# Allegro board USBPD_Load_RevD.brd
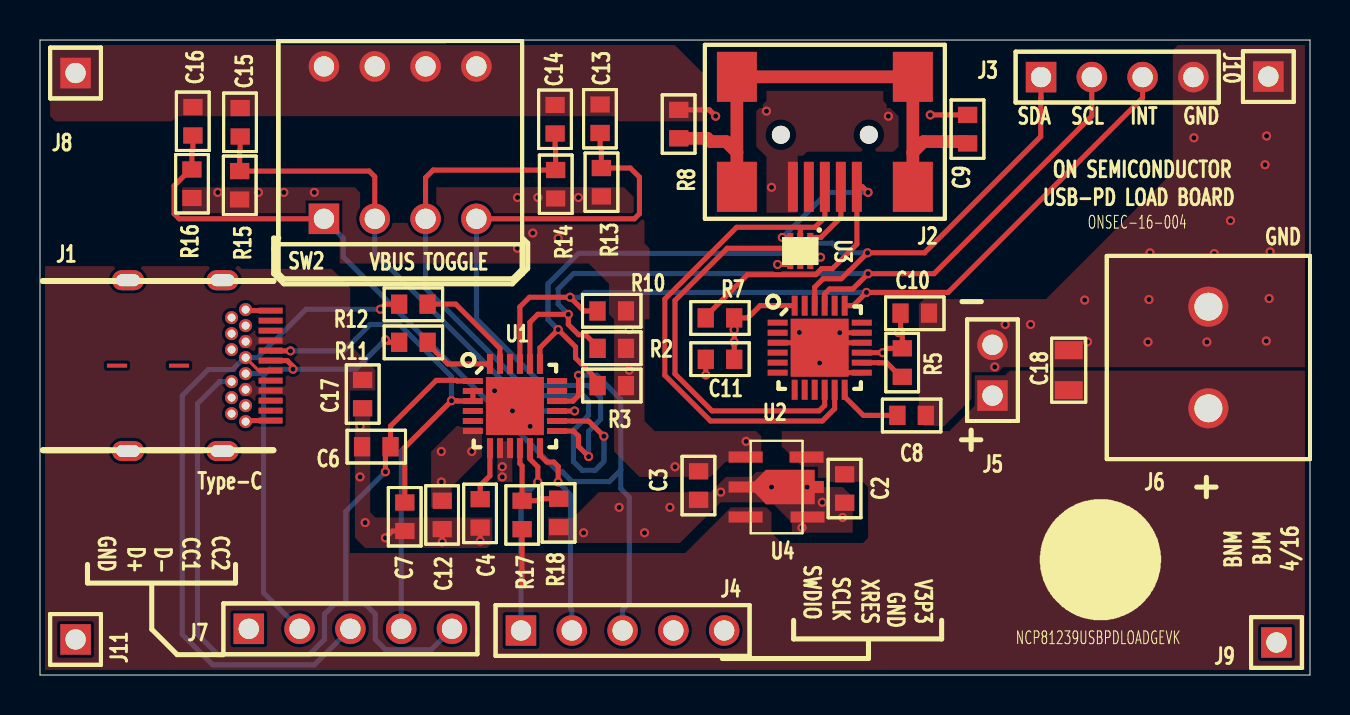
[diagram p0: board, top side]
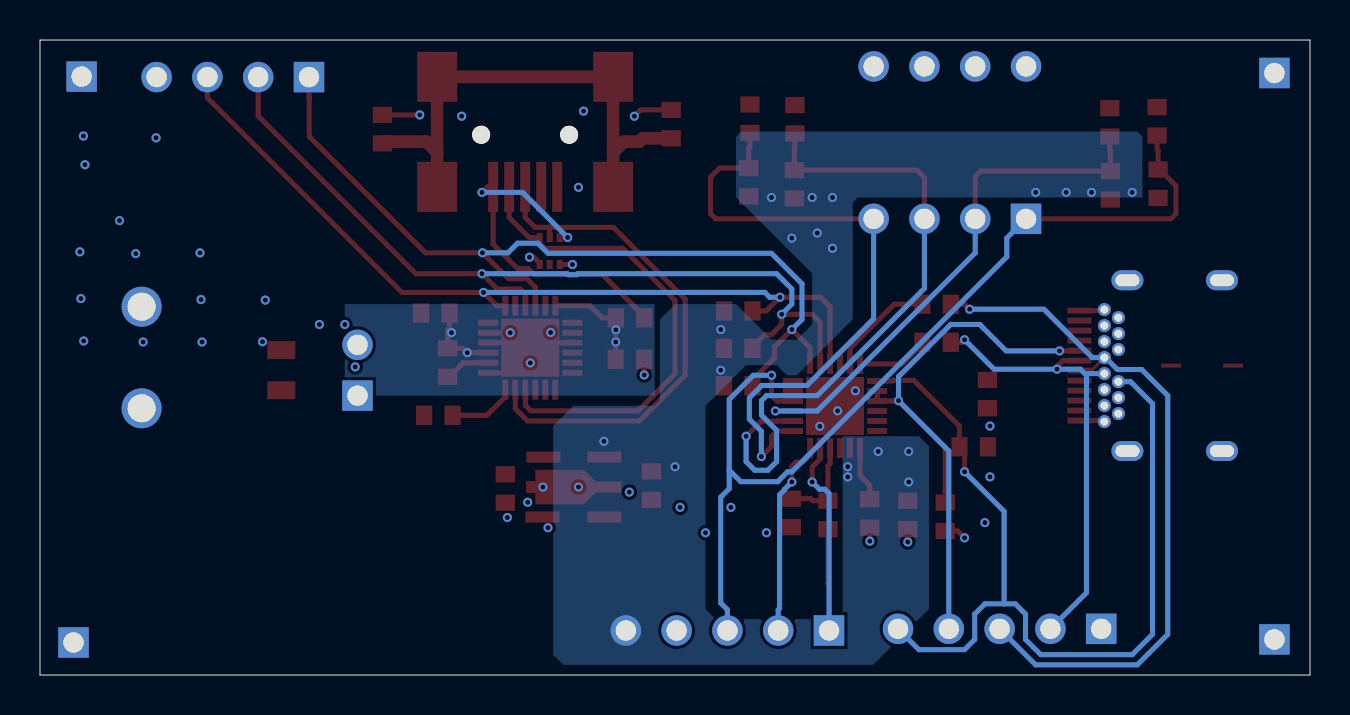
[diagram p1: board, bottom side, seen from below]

Outline 63.5 x 31.75 mm; copper layers: TOP, L2, L3, BOTTOM. Coordinates in mm from the lower left corner of the outline.
Outline path: 0,31.75 0,0 63.5,0 63.5,31.75 0,31.75

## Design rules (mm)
constraint set DEFAULT: min track width 0.152, pair gap 0.15

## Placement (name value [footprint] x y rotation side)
C2  1uF  [SMC0603]  40.23 10.04 270 top
C3  1uF  [SMC0603]  32.93 10.18 270 top
C4  1uF  [SMC0603]  22.01 8.79 270 top
C6  470pF  [SMC0603]  17.53 11.41 180 top
C7  470pF  [SMC0603]  18.24 8.62 270 top
C8  1uF  [SMC0603]  42.87 12.98 0 top
C9  0.1uF  [SMC0603]  46.38 28 270 top
C10  1uF  [SMC0603]  43.03 18.09 0 top
C11  1uF  [SMC0603]  34.71 15.79 180 top
C12  1uF  [SMC0603]  20.11 8.71 270 top
C13  0.1uF  [SMC0603]  28 28.52 270 top
C14  0.1uF  [SMC0603]  25.76 28.5 270 top
C15  0.1uF  [SMC0603]  10.01 28.35 270 top
C16  0.1uF  [SMC0603]  7.65 28.4 270 top
C17  0.1uF  [SMC0603]  16.13 13.34 90 top
C18  2.2uF  [SMC0805]  51.44 15.24 90 top
J1  632 723 300 011  [WURTH_USBPD_TYPE_C]  11.83 20.27 270 top
J2  65100516121  [CON_MINIUSB2-STND_B]  45.14 31.41 180 top
J3  613 004 111 21  [JTHI_HDR1R4PS_100MIL]  50.05 29.9 270 top
J4  613 005 111 21  [JTHI_HDR1R5PS_100MIL]  24.05 2.23 270 top
J5  613 002 111 21  [JTHI_HDR1R2PS_100MIL]  47.62 13.97 0 top
J6  1716020000  [WEIDMULLER-171602000]  58.42 15.88 270 top
J7  613 005 111 21  [JTHI_HDR1R5PS_100MIL]  10.44 2.31 270 top
J8  613 001 111 21  [JTHI_HDR1R1PS_100MIL]  1.78 30.1 0 top
J9  613 001 111 21  [JTHI_HDR1R1PS_100MIL]  61.82 1.63 0 top
J10  613 001 111 21  [JTHI_HDR1R1PS_100MIL]  61.42 29.92 0 top
J11  613 001 111 21  [JTHI_HDR1R1PS_100MIL]  1.78 1.78 0 top
NOREF  -  []  -210.13 -351.74 0 top
NOREF#2  -  []  49.89 2.59 0 top
NOREF#3  -  []  405.08 -332.71 0 top
NOREF#4  -  []  0 0 90 top
NOREF#5  -  []  0 0 0 top
NOREF#6  -  []  653.47 -351.74 180 bottom
NOREF#7  -  []  39.93 -332.59 180 bottom
R2  2.2k  [SMR0603]  29.3 16.33 180 top
R3  2.2k  [SMR0603]  29.3 14.47 180 top
R5  4.7k  [SMR0603]  43.11 16.33 270 top
R7  0  [SMR0603]  33.29 17.86 0 top
R8  100k  [SMR0603]  31.94 28.26 270 top
R10  2.2k  [SMR0603]  29.3 18.2 180 top
R11  DNP  [SMR0603]  17.96 16.64 0 top
R12  DNP  [SMR0603]  17.96 18.54 0 top
R13  2.2k  [SMR0603]  28.07 23.93 90 top
R14  2.2k  [SMR0603]  25.78 23.83 90 top
R15  2.2k  [SMR0603]  9.98 23.77 90 top
R16  4.7k  [SMR0603]  7.59 23.85 90 top
R17  100k  [SMR0603]  24.1 7.29 90 top
R18  10k  [SMR0603]  25.93 8.81 270 top
SW2  S_DIP4  [STHI_DIP04]  14.2 22.81 0 top
U1  CYPD2122-24LQXIT  [USMM_QFN24R4X4_0P5_EP_RWK]  23.75 13.45 0 top
U2  CY7C65211-24LTXI  [USMM_QFN24R4X4_0P5_EP_RWK]  38.98 16.37 0 top
U3  NUP4060  [SOT-563-6]  38.01 21.2 270 top
U4  NCP4641H033T1G  [SOT89-5]  36.83 9.4 0 top

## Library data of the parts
C2-C4 C6-C17 R2 R3 R5 R7 R8 R10-R18 = 0603
C18 = CAP_NP
J1 = 632723300011_USB3_1 C PD
J2 = 65100516121_Mini USB1/2 B
J3 = 613 004 111 21_1x4 100mil
J4 J7 = 613 005 111 21_1x5 100mil
J5 = 613 002 111 21_1x2 100mil
J6 = 1716020000_2pin Screw
J8-J11 = 613 001 111 21_1x1 100mil
SW2 = 206-4
U1 = CYPD21XX-24LQXIT
U2 = CY7C65211-24LTXI
U3 = CM1240
U4 = NCP1450-PWM StepUp CNTRL_2

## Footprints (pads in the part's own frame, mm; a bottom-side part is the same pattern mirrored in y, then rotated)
CON_MINIUSB2-STND_B
  round 0.899 hole 0.899 unplated: (3.701,4.399) (8.1,4.399)
  rect 0.5x2.499 smd: 1(4.3,7) 2(5.1,7) 3(5.9,7) 4(6.701,7) 5(7.501,7)
  rect 1.999x2.499 smd: 6(1.501,7) 7(10.3,7) 8(1.501,1.501) 9(10.3,1.501)
JTHI_HDR1R1PS_100MIL
  rect 1.524x1.524 hole 1.016: 1(0,0)
JTHI_HDR1R2PS_100MIL
  rect 1.524x1.524 hole 1.016: 1(0,0)
  round 1.524 hole 1.016: 2(0,2.54)
JTHI_HDR1R4PS_100MIL
  rect 1.524x1.524 hole 1.016: 1(0,0)
  round 1.524 hole 1.016: 2(0,2.54) 3(0,5.08) 4(0,7.62)
JTHI_HDR1R5PS_100MIL
  rect 1.524x1.524 hole 1.016: 1(0,0)
  round 1.524 hole 1.016: 2(0,2.54) 3(0,5.08) 4(0,7.62) 5(0,10.16)
SMC0603
  rect 0.813x0.965 smd: 1(0,0) 2(1.422,0)
SMC0805
  rect 0.899x1.4 smd: 1(-1.001,0) 2(1.001,0)
SMR0603
  rect 0.813x0.965 smd: 1(0,0) 2(1.422,0)
SOT89-5
  rect 1.702x0.559 smd: 1(-1.549,1.499) 2(-1.549,0) 3(-1.549,-1.499) 4(1.549,-1.499) 5(1.499,1.499)
SOT-563-6
  rect 0.457x0.305 smd: 1(-0.676,0.5) 2(-0.676,0) 3(-0.676,-0.5) 4(0.676,-0.5) 5(0.676,0) 6(0.676,0.5)
STHI_DIP04
  rect 1.524x1.524 hole 1.016: 1(0,0)
  round 1.524 hole 1.016: 2(2.54,0) 3(5.08,0) 4(7.62,0) 5(7.62,7.62) 6(5.08,7.62) 7(2.54,7.62) 8(0,7.62)
USMM_QFN24R4X4_0P5_EP_RWK
  rect 1.001x0.3 smd: 1(-2.103,1.25) 2(-2.103,0.749) 3(-2.103,0.249) 4(-2.103,-0.249) 5(-2.103,-0.749) 6(-2.103,-1.25) 13(2.103,-1.25) 14(2.103,-0.749) 15(2.103,-0.249) 16(2.103,0.249) 17(2.103,0.749) 18(2.103,1.25)
  rect 0.3x1.001 smd: 7(-1.25,-2.103) 8(-0.749,-2.103) 9(-0.249,-2.103) 10(0.249,-2.103) 11(0.749,-2.103) 12(1.25,-2.103) 19(1.25,2.103) 20(0.749,2.103) 21(0.249,2.103) 22(-0.249,2.103) 23(-0.749,2.103) 24(-1.25,2.103)
  rect 2.901x2.901 smd: EPAD(0,0)
WEIDMULLER-171602000
  round 1.999 hole 1.4: 1(-2.54,0) 2(2.54,0)
WURTH_USBPD_TYPE_C
  rect 0.3x1.199 smd: A1(2.05,-0.3) A2(2.55,-0.3) A3(3.051,-0.3) A4(3.551,-0.3) A5(4.049,-0.3) A6(4.549,-0.3) A7(5.05,-0.3) A8(5.55,-0.3) A9(6.05,-0.3) A10(6.551,-0.3) A11(7.051,-0.3) A12(7.549,-0.3)
  round 0.65 hole 0.399: B1(7.6,-1.549) B2(7.201,-2.25) B3(6.401,-2.25) B4(5.999,-1.549) B5(5.601,-2.25) B6(5.199,-1.549) B7(4.399,-1.549) B8(4,-2.25) B9(3.599,-1.549) B10(3.2,-2.25) B11(2.4,-2.25) B12(1.999,-1.549) G1(6.8,-1.549) G2(2.799,-1.549)
  rect 0.201x1.001 smd: M1(4.801,-4.879) M2(4.801,-7.981)
  oval 1.001x1.6 hole 0.599x1.199: SH1(0.531,-2.7) SH2(9.07,-2.7) SH3(0.531,-7.429) SH4(9.07,-7.429)

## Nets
GND: C2.2 C3.2 C4.2 C6.2 C7.2 C8.2 C9.1 C10.2 C11.2 C12.2 C13.1 C14.1 C15.1 C16.1 C17.1 C18.2 J1.A1 J1.A12 J1.B1 J1.B12 J1.G1 J1.G2 J1.SH1 J1.SH2 J1.SH3 J1.SH4 J2.5 J3.4 J4.4 J5.2 J6.1 J7.1 J8.1 J9.1 J10.1 J11.1 R8.1 R18.2 SW2.5 SW2.6 SW2.7 SW2.8 U1.EPAD U2.3 U2.13 U2.16 U2.17 U2.EPAD U3.4 U3.6 U4.2 U4.4
GND_EARTH: C9.2 J2.6 J2.7 J2.8 J2.9 R8.2
V3P3: C3.1 C12.1 J4.5 R2.1 R3.1 R10.1 R13.1 R14.1 R15.1 R16.1 U1.6 U1.8 U1.9 U4.1(VOUT)
V5P0: C10.1 C11.1 R5.1 R7.2 U2.15 U2.24
VBUS: C2.1 C17.2 C18.1 J1.A4 J1.A9 J1.B4 J1.B9(VBUS_4) J5.1 J6.2 R17.1 U4.3 U4.5
VBUS_MINI: J2.1(VBUS) R7.1 U3.3(VCC)
CC1: C7.1 J1.A5 J7.4 U1.2 U1.3
CC2: C6.1 J1.B5 J7.5 U1.1
D+: J1.A6 J1.B6 J7.2 R11.1
D-: J1.A7 J1.B7 J7.3 R12.1
GPIO2: C13.2 R13.2 SW2.4 U1.13
GPIO3: C14.2 R14.2 SW2.3 U1.14
GPIO4: C15.2 R15.2 SW2.2 U1.15
GPIO8: R17.2 R18.1 U1.10
INT: J3.3 R10.2 U1.21 U2.19
SCL: J3.2 R2.2 U1.20 U2.21
SCLK: J4.2 U1.12
SDA: J3.1 R3.2 U1.19 U2.22
SWDIO: J4.1 U1.11
XRES: C16.2 J4.3 R16.2 SW2.1 U1.16(XRES)
N13979004: J2.2 U2.10 U3.1
N13979011: J2.3 U2.11 U3.2
N13982640: C4.1 U1.7
N13984820: R5.2 U2.14
N13984928: C8.1 U2.12
N14015838: R11.2 U1.24
N14015876: R12.2 U1.23

Pads without a net: J1 A2 A3 A8 A10 A11 B2 B3 B8 B10 B11 M1 M2; J2 4; U1 4 5 17 18 22; U2 1 2 4 5 6 7 8 9 18 20 23; U3 5

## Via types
v1: diameter 0.457, hole 0.254, TOP to BOTTOM, 90 vias

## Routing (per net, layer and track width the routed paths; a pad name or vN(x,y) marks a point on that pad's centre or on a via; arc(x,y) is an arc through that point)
GND: length 52.2
  TOP w0.254: C12.2 v1(20.11,6.65) ; J1.A1 10.33,18.22 J1.B12 ; U2.17 v1(39.99,17.11) 39.23,16.61 ; 39.23,16.61 U2.EPAD ; 39.23,16.61 U2.16 ; U2.EPAD 38.73,16.61 U2.3 ; U2.EPAD 40.23,15.12 U2.13 ; v1(39.02,20.89) 38.8,20.89 38.51,20.6 U3.6 ; v1(33.78,27.94) 33.46,28.26 R8.1 ; C9.1 v1(44.51,28) ; C4.2 v1(22.01,6.69) ; v1(17.27,6.86) 17.61,7.2 C7.2 ; U3.4 v1(36.88,20.53) ; J1.B1 10.33,12.72 J1.A12 ; C11.2 v1(33.29,15)
  L2 w0.508: J1.SH4 5.56,11.2 ; J1.SH4 4.4,10.34 ; J1.SH4 4.4,12.06 ; J1.SH4 3.24,11.2 ; J1.SH2 10.29,11.2 ; J1.SH2 9.13,10.34 ; J1.SH2 9.13,12.06 ; J1.SH2 7.97,11.2 ; J1.SH3 5.56,19.74 ; J1.SH3 4.4,18.88 ; J1.SH3 3.24,19.74 ; J1.SH3 4.4,20.6 ; 7.97,19.74 J1.SH1 ; J1.SH1 10.29,19.74 ; J1.SH1 9.13,18.88 ; J1.SH1 9.13,20.6
  L3 w0.508: J1.SH4 5.56,11.2 ; J1.SH4 3.24,11.2 ; J1.SH4 4.4,12.06 ; J1.SH4 4.4,10.34 ; J1.SH1 10.29,19.74 ; J1.SH1 7.97,19.74 ; J1.SH1 9.13,20.6 ; J1.SH1 9.13,18.88 ; 4.4,18.88 J1.SH3 ; J1.SH3 5.56,19.74 ; J1.SH3 4.4,20.6 ; J1.SH3 3.24,19.74 ; 7.97,11.2 J1.SH2 ; J1.SH2 10.29,11.2 ; J1.SH2 9.13,12.06 ; J1.SH2 9.13,10.34
  vias: v1(16,12.45) v1(16,9.91) v1(16.26,7.62) v1(22.73,14.21) v1(23.62,13.21) v1(24.51,12.43) v1(27.18,7.11) v1(28.96,8.38) v1(30.23,7.11) v1(31.5,8.38) v1(34.04,9.14) v1(36.32,28.19) v1(36.58,24.38) v1(36.58,9.4) v1(37.97,17.13) v1(38.1,7.37) v1(38.35,9.4) v1(38.98,15.6) v1(39.12,8.64) v1(40.13,7.87) v1(42.42,27.94) v1(47.74,15.41) v1(48.26,17.53) v1(49.53,17.53) v1(52.24,18.75) v1(52.37,16.66) v1(55.45,18.77) v1(55.4,16.65) v1(55.5,21.11) v1(57.7,26.86) v1(58.34,16.65) v1(58.71,21.07) v1(59.52,22.72) v1(61.33,26.95) v1(61.25,25.51) v1(61.32,16.7) v1(61.51,21.16) v1(61.46,18.82)
GND_EARTH: length 26
  TOP w0.635: R8.2 33.36,26.84 33.53,26.67 34.31,26.67 34.84,26.13 ; C9.2 46.29,26.67 44.18,26.67 43.64,26.13 ; 34.84,26.13 J2.9 J2.8 43.64,26.13 ; 34.84,26.13 J2.7 ; 43.64,26.13 J2.6
V3P3:
  vias: v1(8.89,24.13) v1(10.92,24.13) v1(12.19,24.13) v1(13.72,24.13) v1(20.07,11.18) v1(20.07,9.65) v1(21.59,11.18) v1(23.11,10.41) v1(23.11,9.91) v1(23.88,23.88) v1(23.88,21.34) v1(24.64,22.1) v1(24.89,23.88) v1(25.91,21.84) v1(26.92,23.88) v1(29.46,17.27) v1(29.46,15.24) v1(31.75,10.41) v1(35.31,11.68)
V5P0: length 9.5
  TOP w0.254: 43.03,17.33 43.03,17.22 v1(42.93,17.12) ; 43.03,17.33 C10.1 ; 43.03,17.33 43.11,17.25 R5.1 42.35,16.33 v1(42.14,16.12) U2.15 ; U2.24 36.01,18.47 35.39,17.86 R7.2 34.71,17.26 v1(34.71,17.26) 34.71,17.26 34.71,16.65 v1(34.71,16.65) C11.1
VBUS: length 2.7
  TOP w0.254: R17.1 24.1,4.6 24.13,4.57
VBUS_MINI: length 18.3
  TOP w0.254: U3.3 v1(37.12,21.88) ; R7.1 33.29,17.93 35.37,20.02 38.78,20.02 39.09,20.32 39.62,20.32 40.84,21.54 J2.1 41.12,24.41 v1(41.4,24.13)
  BOTTOM w0.254: v1(41.4,24.13) 39.37,24.13 v1(37.12,21.88)
CC1: length 32
  TOP w0.254: C7.1 18.24,11.38 v1(20.57,13.72) 20.85,13.72 20.86,13.7 U1.3 U1.2 ; v1(12.52,16.21) 11.54,16.21 J1.A5
  BOTTOM w0.254: v1(12.52,16.21) 15.19,16.21 16.51,17.53 17.97,17.53 20.57,14.92 v1(20.57,13.72) 18.06,11.2 J7.4
CC2: length 45.7
  TOP w0.254: v1(17.27,10.16) 17.27,11.16 C6.1 17.53,12.45 19.81,14.73 20.83,14.73 20.86,14.7 U1.1
  BOTTOM w0.254: 15.29,3.56 16.25,3.56 16.76,3.05 16.76,1.78 17.27,1.27 19.56,1.27 J7.5 ; 15.29,3.56 15.29,8.18 v1(17.27,10.16) ; 15.29,3.56 14.73,3.56 14.22,3.05 14.22,1.78 13.46,1.02 8.89,1.02 7.87,2.03 7.87,13.57 8.97,14.67 J1.B5
D+: length 23.3
  TOP w0.254: J1.A6 12.36,15.72 12.65,15.43 v1(12.65,15.29) ; v1(17.27,16.76) 17.4,16.64 R11.1
  BOTTOM w0.254: 11.18,14.99 11.48,15.29 v1(12.65,15.29) 15.8,15.29 v1(17.27,16.76) ; 11.18,14.99 11.18,4.11 J7.2 ; 11.18,14.99 11.09,15.07 J1.B6
D-: length 36
  TOP w0.152: J1.A7 10.93,15.22 J1.B7
  TOP w0.254: R12.1 17.27,18.54 v1(17.02,18.29)
  BOTTOM w0.254: v1(17.02,18.29) 13.3,18.29 10.88,15.87 J1.B7 10.22,15.87 9.63,15.27 8.42,15.27 7.11,13.97 7.11,2.03 8.64,0.51 13.72,0.51 J7.3
GPIO2: length 32.4
  TOP w0.254: v1(27.43,10.92) 26.92,11.43 26.92,11.95 26.67,12.2 U1.13 ; C13.2 28,26.42 28.07,26.35 R13.2 29.51,25.35 29.97,24.89 29.97,23.06 29.72,22.81 SW2.4
  BOTTOM w0.254: v1(27.43,10.92) 27.43,12.19 28.03,12.79 28.03,13.86 27.41,14.48 25.15,14.48 21.82,17.81 SW2.4
GPIO3: length 33.7
  TOP w0.254: v1(28.19,11.94) 27.44,12.69 26.64,12.69 26.63,12.7 U1.14 ; C14.2 25.76,26.39 25.78,26.37 R14.2 19.66,25.25 19.28,24.87 SW2.3
  BOTTOM w0.254: SW2.3 19.28,19.33 24.64,13.97 27.17,13.97 27.42,13.72 27.42,12.99 26.67,12.24 26.67,10.67 27.1,10.24 27.76,10.24 28.19,10.67 v1(28.19,11.94)
GPIO4: length 26.6
  TOP w0.254: SW2.2 16.74,24.92 16.46,25.2 R15.2 9.98,26.21 10.01,26.24 C15.2 ; U1.15 v1(26.73,13.2)
  BOTTOM w0.254: SW2.2 16.74,21.11 24.65,13.2 v1(26.73,13.2)
GPIO8: length 4.6
  TOP w0.254: U1.10 24,10.57 24.1,10.46 R17.2 24.87,8.71 24.97,8.81 R18.1
INT: length 42.4
  TOP w0.254: J3.3 55.13,28.85 45.41,19.13 v1(41.32,19.13) 40.66,18.47 U2.19 ; U1.21 24,18.41 24.48,18.89 v1(26.5,18.89) 27.19,18.2 R10.2
  BOTTOM w0.254: v1(26.5,18.89) 27.02,18.89 27.26,19.13 v1(41.32,19.13)
SCL: length 43.6
  TOP w0.254: J3.2 52.59,27.95 44.7,20.07 v1(41.4,20.07) 40.64,19.3 39.49,19.3 39.23,19.05 U2.21 ; R2.2 27.88,16.41 27.27,17.01 26.93,17.01 26.42,17.53 v1(26.42,18.03) 24.89,18.03 24.5,17.64 U1.20
  BOTTOM w0.254: v1(26.42,18.03) 25.91,18.54 25.91,19.3 26.67,20.07 36.62,20.07 36.67,20.02 37.09,20.02 37.14,20.07 v1(41.4,20.07)
SCLK: length 10
  TOP w0.254: U1.12 25,11 25.34,10.65 25.69,10.65 25.91,10.43 v1(25.91,9.65)
  BOTTOM w0.254: J4.2 26.59,3.27 26.52,3.33 26.52,9.01 26.27,9.26 26.27,9.29 v1(25.91,9.65)
SDA: length 43.6
  TOP w0.254: R3.2 27.88,14.75 26.78,15.85 26.78,16.4 v1(25.91,17.27) 25,16.36 U1.19 ; J3.1 50.05,28.85 50.04,28.84 50.04,26.92 44.22,21.11 v1(41.38,21.11) 40.49,20.22 40.47,20.22 40.07,19.81 39.15,19.81 38.73,19.39 U2.22
  BOTTOM w0.254: v1(41.38,21.11) 40.1,21.11 39.62,21.59 38.61,21.59 38.1,21.08 26.92,21.08 25.4,19.56 25.4,17.78 v1(25.91,17.27)
SWDIO: length 9.8
  TOP w0.254: v1(24.89,9.65) 24.89,10.4 24.5,10.8 U1.11
  BOTTOM w0.254: J4.1 24.05,9.07 24.27,9.29 24.53,9.29 v1(24.89,9.65)
XRES: length 49.7
  TOP w0.254: v1(26.92,14.99) 26.92,13.97 26.66,13.71 26.64,13.71 26.63,13.7 U1.16 ; SW2.1 6.96,22.81 6.71,23.06 6.71,24.46 7.52,25.27 R16.2 7.59,26.24 7.65,26.29 C16.2
  BOTTOM w0.254: SW2.1 15.16,21.85 15.16,20.91 25.91,10.16 26.12,10.16 26.61,9.67 28.46,9.67 29.04,10.24 ; 29.04,10.24 29.04,9.31 29.46,8.89 29.46,3.6 29.13,3.27 J4.3 ; 29.04,10.24 29.04,13.78 27.83,14.99 v1(26.92,14.99)
N13979004: length 24.5
  TOP w0.254: J2.2 40.04,22.88 39.04,21.88 U3.1 38.51,21.59 38.26,21.34 34.36,21.34 31.75,18.73 31.75,15.05 33.6,13.21 38.96,13.21 39.23,13.48 U2.10
N13979011: length 26.2
  TOP w0.254: 38.01,22.39 38.75,22.39 39.24,22.88 39.24,24.41 ; 38.01,22.39 U3.2 ; 38.01,22.39 34.83,22.39 31.24,18.8 31.24,14.99 33.53,12.7 39.12,12.7 39.73,13.32 U2.11
N13982640: length 2.8
  TOP w0.254: U1.7 22.5,9.96 22.01,9.48 C4.1
N13984820: length 2.3
  TOP w0.254: R5.2 43.04,14.91 42.34,15.61 41.93,15.61 41.92,15.62 U2.14
N13984928: length 3.4
  TOP w0.254: U2.12 40.23,13.91 41.16,12.98 C8.1
N14015838: length 3.6
  TOP w0.254: R11.2 19.38,16.56 20.39,15.55 U1.24
N14015876: length 5.3
  TOP w0.254: R12.2 20.79,18.54 23,16.33 U1.23

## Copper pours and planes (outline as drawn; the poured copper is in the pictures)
GND on TOP (solid shape): 38.73,9.7 39.19,9.7 39.19,9.09 38.73,9.09 38.73,8.53 36.3,8.53 35.74,9.12 35.74,9.7 36.3,10.26 38.73,10.26
GND on TOP: 37.59,7.11 40.64,7.11 40.64,8.89 40.13,9.4 39.12,9.4 38.35,10.16 35.81,10.16 35.56,9.91 34.29,9.91 33.53,9.14 27.94,9.14 26.67,7.87 25.4,7.87 25.4,6.6 32,6.6 34.04,8.64 36.58,8.64 37.59,7.62
GND on TOP: 22.61,7.87 16.76,7.87 16.51,8.13 16.51,13.72 15.75,13.72 15.75,6.86 16.26,6.35 22.35,6.35 22.61,6.6
GND on TOP: 50.29,18.8 44.2,18.8 43.94,18.54 43.94,12.7 44.2,12.45 45.21,12.45 48.16,15.39 63.25,15.39 63.25,31.5 56.9,31.5 56.64,31.24 56.64,25.15
GND on TOP: 33.27,27.69 28.96,27.69 28.7,27.94 6.86,27.94 6.6,27.69 0.76,27.69 0.51,27.94 0.51,31.5 31.75,31.5 33.27,29.97
GND on TOP: 37.85,23.11 37.85,25.65 38.35,26.16 42.67,26.16 42.93,26.42 42.93,27.94 42.16,28.7 42.16,29.21 36.32,29.21 36.32,28.7 35.81,28.19 35.81,26.42 36.32,25.91 36.32,23.11
GND on L2, L3: 0.25,0.25 0.25,31.5 63.25,31.5 63.25,0.25
V3P3 on TOP: 7.11,24.38 7.11,22.86 13.97,22.86 14.99,21.84 14.99,20.57 27.43,20.57 28.45,19.56 28.45,18.03 28.7,17.78 30.48,17.78 30.48,21.34 30.23,21.59 30.23,23.37 29.21,24.38 19.81,24.38 19.81,22.61 16.51,22.61 16,23.11 16,24.13 15.75,24.38
V3P3 on TOP: 36.07,10.67 34.29,10.67 33.53,9.91 29.97,9.91 28.7,11.18 28.7,18.54 28.96,18.8 30.23,18.8 30.23,12.7 30.73,12.19 35.81,12.19 36.07,11.94
V3P3 on TOP: 22.86,11.68 22.86,9.65 23.62,9.65 23.62,11.68
V3P3 on TOP: 23.62,24.38 23.62,23.37 28.7,23.37 28.7,24.38
V3P3 on TOP: 22.1,10.92 20.57,9.4 20.57,8.38 19.56,8.38 19.56,11.18 20.83,12.45 22.1,12.45
V3P3 on BOTTOM: 21.84,0.51 19.05,3.3 19.05,11.43 19.56,11.94 23.37,11.94 23.37,2.79 29.72,2.79 30.23,3.3 30.23,13.46 28.19,15.49 26.67,15.49 26.16,14.99 25.65,14.99 22.86,17.78 22.86,23.62 22.61,23.88 8.38,23.88 8.38,26.92 8.64,27.18 28.45,27.18 28.7,26.92 28.7,23.88 24.89,20.07 24.89,17.53 25.65,16.76 26.92,16.76 28.7,18.54 31.75,18.54 32.51,17.78 32.51,13.72 32.77,13.46 36.83,13.46 37.85,12.45 37.85,1.02 37.34,0.51
V5P0 on BOTTOM: 32.77,18.54 32.77,13.97 48.26,13.97 48.26,18.54
VBUS on TOP: 63.25,15.21 63.25,0.25 0.25,0.25 0.25,20.5 0.31,20.44 9.95,20.44 10.08,20.31 14.58,20.31 15.51,19.38 15.51,16.51 16.76,15.25 16.76,14.22 15.51,14.22 15.51,9.4 15.49,9.39 15.49,6.1 32.26,6.1 34.54,8.38 36.32,8.38 36.58,8.13 36.58,7.11 37.08,6.6 41.15,6.6 41.4,6.86 41.4,9.4 41.15,9.65 38.86,9.65 37.08,11.43 37.08,12.19 45.47,12.19 46.74,13.46 46.74,14.99 48.26,14.99 48.49,15.21

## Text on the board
Ref Des/Assembly Bottom: SECONDARY SIDE ASSEMBLY VIEWED FROM SECONDARY SIDE
User.Comments: SCALE | SIZE | DWG NO | SHEET | Brian Markus | 2/08/16 | UNLESS OTHERWISE SPECIFIED | SIGNATURES | DATE | TOLERANCES ON: | ANGLES +/- 1.0 DEGREE | 3 PL DECIMALS +/- .015 | 2 PL DECIMALS +/- .005 | DIMENSIONS ARE IN INCHES | ENG: | DRAWN: | ISSUED: | CHECKED: | D | 1/1 | USE PURSUANT TO COMPANY INSTRUCTIONS | ONSEC-16-004 | 1 OF 2 | ASSEMBLY NOTES: | ON Semiconductor | USB-PD Load Board
Ref Des/Silkscreen Top: NCP81239USBPDLOADGEVK | ONSEC-16-004 | Type-C | VBUS TOGGLE | SDA | SCL | USB-PD LOAD BOARD | ON SEMICONDUCTOR | INT | GND | BNM | BJM | 4/16 | D+ | D- | CC1 | CC2 | SWDIO | SCLK | XRES | V3P3
XSECTION_CHART: *  SURFACE - AIR 0 MIL | L1 TOP CONDUCTOR - COPPER 1.9 MIL | *  DIELECTRIC - FR-4 4 MIL | L2 L2 PLANE - COPPER 1.2 MIL | *  DIELECTRIC - FR-4 47.8 MIL | L3 L3 CONDUCTOR - COPPER 1.2 MIL | L4 BOTTOM CONDUCTOR - COPPER 1.9 MIL | DESIGN CROSS SECTION CHART | ___________________________ | TOTAL THICKNESS 62 MIL | 1-4 | ASSEMBLY NOTES:
PAGE_OUTLINE: E | D | B | C | A | 6 | 5 | 4 | 3 | 2 | 1
DIMENSION: A | C | B | E | D | 1 | 2 | 3 | 4 | 5 | 6
BODY_CENTER: 2/08/16 | Brian Markus | DIMENSIONS ARE IN INCHES | 2 PL DECIMALS +/- .005 | 3 PL DECIMALS +/- .015 | ANGLES +/- 1.0 DEGREE | TOLERANCES ON: | 2 OF 2 | ONSEC-16-004 | USE PURSUANT TO COMPANY INSTRUCTIONS | 1/1 | D | ON Semiconductor | USB-PD Load Board
User.6: SHEET | DWG NO | SIZE | SCALE | DATE | SIGNATURES | CHECKED: | ISSUED: | DRAWN: | ENG: | UNLESS OTHERWISE SPECIFIED
User.7: INSPECT TO IPC-A-600. | NOTES: | 1. PRINTED CIRCUIT BOARD IS SHOWN VIEWED FROM COMPONENT SIDE. | 2. ALL MATERIALS TO BE ROHS COMPLIANT. | FABRICATE PER IPC-6012 AND IPC-6011. | 3. BOARD MATERIAL: ROHS COMPLIANT FR-4, LAMINATED SHEET, HTE COPPER CLAD, | 4. FINISH; | 10. CONTROLLED IMPEDANCE 68 OHMS +/-15%. | A. PLATED HOLES SHALL HAVE A MINIMUM COPPER THICKNESS | IT'S RESPECTIVE CIRCUIT LAYER, NO MASK ON PADS. | C. PLATING TO BE ROHS COMPLIANT, IMMERSION SILVER, PER IPC-4553. | B. LPI SOLDERMASK, GREEN, PER IPC-SM-840 OVER BARE COPPER (SMOBC). | SOLDERMASK REGISTRATION TO BE WITHIN +/- .003 OF | OF .0008 IN. AND HAVE A MINIMUM OF 80% COVERAGE. | D. HOLE DIMENSIONS APPLY AFTER FINISHING. | E. HOLE TOLERANCE; +/- .003 PLATED AND +/- .005 NON-PLATED UNLESS OTHERWISE NOTE. | HOLES .018 AND UNDER MAY BE PLUGGED. | 6. UL RECOGNIZED VENDOR MARK AND 94V-0 | 5. SILKSCREEN WITH ROHS COMPLIANT WHITE NON-CONDUCTIVE INK, NO INK ON PADS. | TO APPEAR ON SOLDERSIDE IN ETCH, | 11 PADS LOCATED WITHIN THIS AREA SHALL BE | 12 REFERENCE DIMENSIONS AND CENTERLINES SPECIFY V-GROOVE LOCATIONS. | ROHS COMPLIANT SYMBOL TO APPEAR ON SOLDERSIDE IN | ROHS COMPLIANT WHITE NON-CONDUCTIVE INK ONLY. | ROHS COMPLIANT WHITE NON-CONDUCTIVE INK OR LASER MARKING. | 8. FOR COPPER WEIGHT AND BOARD THICKNESS SEE DETAIL 'A'. | 7. WRAP AND TWIST NOT TO EXCEED .010 IN./IN. | 9. LAYER TO LAYER REGISTRATION .005 IN. | THIS BOARD HAS 2 LAYERS. | TYPE GF/GFG, WOVEN GLASS BASE, FLAME RESISTANT, MEETING UL-94V0 OR BETTER. | Tg RATING OF 130 DEGREES C OR GREATER. Td RATING OF 340 DEGREES C OR GREATER | BONDING MATERIAL: ROHS COMPLIANT PLASTIC SHEET, TYPE GF/GFG BASE MATERIAL, | GLASS BASE PRE-IMPREGNATED (B-STAGE). | Tg RATING 130 C OR GREATER. Td RATING OF 340 DEGREES C OR GREATER | MATERIAL IN ACCORDANCE WITH IPC-4101. | 200 MICRO INCHES NICKEL. | PLATED 30 TO 50 MICRO INCHES GOLD OVER | .010 +.003/-.003 WEB SHALL BE LEFT AFTER PROCESSING.
User.8: FIGURE | FINISHED_SIZE | 55.1 | 40.0 | 15.7 | 10.0 | 35.4 | 47.2x23.6 | TOLERANCE_DRILL | +3.0/-3.0 | +4.0/-4.0 | +2.0/-2.0 | DRILL CHART: TOP to BOTTOM | ALL UNITS ARE IN MILS | TOLERANCE_TRAVEL | - | PLATED | NON-PLATED | QTY | 2 | 28 | 14 | 90 | 4
